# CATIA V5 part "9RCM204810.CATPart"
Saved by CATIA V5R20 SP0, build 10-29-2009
Part number: 9RCM204810
Revision: ANY
Definition: UNKNOWN
Nomenclature: 9RCM204810
Source: Unknown
Bounding box of the stored display mesh (mm): x -38 to 9.95, y -9.95 to 9.95, z -4.35 to 4.35
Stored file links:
  C:\Users\Utente\Desktop\IO LAVORO\3D X SITO CF\CUMSA\3D files RCM\RCM 204810\9RCM204810.CATPart
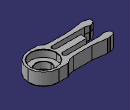
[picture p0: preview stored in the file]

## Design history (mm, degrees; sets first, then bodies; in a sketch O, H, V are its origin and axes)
Body1 "Chaflán2" (main body)
  Solid1: solid without history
